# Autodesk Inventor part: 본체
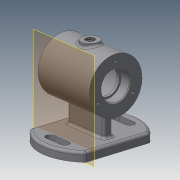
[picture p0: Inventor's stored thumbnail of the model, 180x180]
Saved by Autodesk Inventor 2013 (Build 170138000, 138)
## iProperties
Created: 2021-09
Part Number: 본체
Material: 일반
Document SubType Name: Modeling
Designer: kum
Density: 1 g/cm^3
Author: kum
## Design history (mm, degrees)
sketch "스케치1"
  geometry: L1 (37.5, -36.742)-(37.5, 36.742); L2 (-37.5, -36.742)-(-37.5, 36.742); A1 r 52.5 centre (0, 0) between (-37.5, -36.742) and (37.5, -36.742); A2 r 52.5 centre (0, 0) between (37.5, 36.742) and (-37.5, 36.742); 1 further point
  constraints: 4 end point, 4 point on circle, 2 centre point, 1 coincident, 1 parallel, 1 vertical
  dimensions: "d8" = 37.5 distance from line of A1.centre L1; "d9" = 37.5 distance from line of point (0, 0) L2; "d10" = 52.5 radius of A1; "d11" = 52.5 radius of A2
extrude "돌출1" new body sketch "스케치1" distance "d5" = 10; taper "d6" = 0 deg
sketch "스케치5"
  geometry: L1 (0, 36.742)-(0, -36.742) reference; C1 r 30 at (62, 0); 2 further points
  constraints: 1 centre point, 1 horizontal alignment, 1 midpoint
  dimensions: "d20" = 60 diameter of C1; "d22" = 62 distance of point (0, 0) C1.centre
extrude "돌출4" join sketch "스케치5" stored distance "d23" = 70; taper "d24" = 0 deg
sketch "스케치6"
  geometry: L1 (-25, -5)-(25, -5); L2 (25, -5)-(25, 5); L3 (25, 5)-(-25, 5); L4 (-25, 5)-(-25, -5); L5 (-25, -5)-(25, 5); L6 (25, -5)-(-25, 5); A1 r 52.5 centre (0, 0) between (37.5, 36.742) and (-37.5, 36.742) reference
  constraints: 12 end point, 2 midpoint, 2 parallel, 1 horizontal, 1 perpendicular
  dimensions: "d25" = 50 distance of L3.end L2.end; "d26" = 10 distance of L2.end L1.end
extrude "돌출5" join sketch "스케치6" stored distance "d27" = 70; taper "d28" = 0 deg
sketch "스케치7"
  geometry: L1 (-35, 92)-(-35, 32) reference; L2 (35, 32)-(35, 92) reference; L3 (-35, 62)-(35, 62); L4 (-35, 62)-(-35, 78); L5 (-35, 78)-(-23, 78); L6 (-23, 78)-(-23, 76); L7 (-23, 76)-(-20, 76); L8 (-20, 76)-(-20, 87); L9 (-20, 87)-(20, 87); L10 (20, 87)-(20, 76); L11 (20, 76)-(23, 76); L12 (23, 76)-(23, 78); L13 (23, 78)-(35, 78); L14 (35, 78)-(35, 62); 1 further point
  constraints: 24 end point, 6 parallel, 3 perpendicular, 2 midpoint, 2 point on line, 1 collinear
  dimensions: "d29" = 32 diameter of L5 L3; "d31" = 28 diameter of L7 L3; "d32" = 50 diameter of L9 L3; "d33" = 28 diameter of L11 L3; "d34" = 32 diameter of L13 L3; "d35" = 12 distance between parallel lines of L2 L12; "d36" = 40 distance between parallel lines of L10 L8; "d37" = 12 distance between parallel lines of L6 L4; "d38" = 3 distance between parallel lines of L6 L8
revolve "회전1" sketch "스케치7" stored, may be unused: angle "d39" = 90 deg
node "작업 평면1"
sketch "스케치8"
  geometry: C1 r 10 at (0, 0); 1 further point
  constraints: 1 centre point, 1 coincident
  dimensions: "d41" = 20 diameter of C1
extrude "돌출6" join sketch "스케치8" stored distance "d42" = 70; taper "d43" = 0 deg
sketch "스케치9"
  geometry: C1 r 10 at (0, 0) reference; 1 further point
  constraints: 1 coincident
hole "구멍1" sketch "스케치9" at (0, 0) diameter "d44" = 10.106; stored, may be unused: countersink angle "d48" = 90 deg, drill point angle "d50" = 118 deg; dims "d45" = 28, "d46" = 4, "d47" = 2, "d49" = 30
sketch "스케치10"
  geometry: L1 (0, 23)-(0, 0); L2 (-19.919, -11.5)-(0, 0); L3 (19.919, -11.5)-(0, 0); C1 r 16 at (0, 0) reference; C2 r 30 at (0, 0) reference; A1 r 23 centre (0, 0) between (0, 23) and (19.919, -11.5); 1 further point
  constraints: 6 end point, 3 point on circle, 1 centre point, 1 coincident, 1 vertical, 1 vertical alignment
  dimensions: "d51" = 46 diameter of A1; "d67" = 120 deg angle of L3 L1; "d69" = 120 deg angle of L2 L3
hole "구멍2" sketch "스케치10" at (0, 23), (-19.919, -11.5), (19.919, -11.5) diameter "d52" = 3.242; stored, may be unused: countersink angle "d56" = 90 deg, drill point angle "d58" = 118 deg; dims "d53" = 8, "d54" = 4, "d55" = 2, "d57" = 10
sketch "스케치11"
  geometry: L1 (25, 5)-(25, -5) reference; L2 (-10, -32)-(10, -32); L3 (10, -42)-(-10, -42); A1 r 52.5 centre (0, 0) between (-37.5, -36.742) and (37.5, -36.742) reference; A2 r 5 centre (-10, -37) between (-10, -32) and (-10, -42); A3 r 5 centre (10, -37) between (10, -42) and (10, -32); 1 further point
  constraints: 4 end point, 4 point on circle, 3 tangent, 2 centre point, 1 horizontal alignment, 1 perpendicular, 1 vertical alignment
  dimensions: "d59" = 10 diameter of A3; "d60" = 10 diameter of A2; "d61" = 20 distance of A3.centre A2.centre; "d62" = 37 vertical distance of A2.centre A1.centre; "d63" = 10 distance of A3.centre point (0, -37); "d64" = 10 distance of point (0, -37) A2.centre
extrude "돌출7" cut sketch "스케치11" stored distance "d65" = 70; taper "d66" = 0 deg
fillet "모깎기1" dims "d71" = 0.3
fillet "모깎기2" dims "d72" = 3
chamfer "모따기1" distance "d73" = 1; stored, may be unused: second distance "d74" = 2, angle "d75" = 45 deg
node "작업 평면2"
node "솔리드1"
mirror "대칭1"
mirror "대칭2"
other parameters: "d0" = 105, "d7" = 105, "d40" = 95
